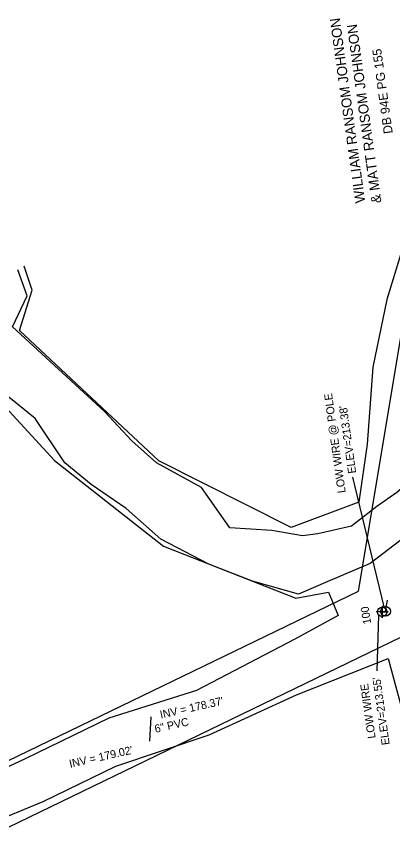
# Model space of a CAD drawing. Extents: x 2317197 to 2318671, y 941884 to 943470.
# Drawn here: x 2318237.5 to 2318425.8, y 942551.5 to 942958 of the extents above; entities that cross this region are included whole.
import ezdxf

# ---------------------------------------------------------------- set-up
doc = ezdxf.new("R2010")
doc.units = 0
for name, color, linetype in [('Default Symbol CELL', 7, 'Continuous'), ('Default Symbol Leader', 7, 'Continuous'), ('Default Symbol Text', 7, 'Continuous'), ('Exist Hydro Jurisdictional Stream or Body of Water', 7, 'Continuous'), ('Exist Property Deed Book Text', 7, 'Continuous'), ('Exist Property Owner Text', 7, 'Continuous'), ('Exist Right of Way Easement Line', 7, 'Continuous'), ('Exist Right of Way Line', 7, 'Continuous'), ('Exist Structure Minor Pipes HDPE 8 Inch', 7, 'Continuous'), ('Exist Structure Minor Pipes HDPE 8 Inch Invert', 7, 'Continuous'), ('Exist Structure Minor Pipes HDPE 8 Inch Text', 7, 'Continuous'), ('Exist Utilities Power Pole CELL', 7, 'Continuous'), ('Exist Utilities Power Pole Text', 7, 'Continuous'), ('Exist Utilities Power Tower CELL', 7, 'Continuous'), ('Exist Vegetation Woods Line', 7, 'Continuous')]:
    doc.layers.add(name, color=color, linetype=linetype)

msp = doc.modelspace()

# ---------------------------------------------------------------- linework, layer by layer
at = {"layer": 'Default Symbol CELL'}
msp.add_lwpolyline([(2318420.6, 942663.37), (2318420.6, 942657.37), (2318420.6, 942660.37), (2318423.6, 942660.37), (2318417.6, 942660.37)], dxfattribs=at)
msp.add_circle((2318420.6, 942660.37), 2.34, dxfattribs=at)
at = {"layer": 'Default Symbol Leader'}
for p, q in [((2318421.59, 942662.95), (2318405.83, 942727.77)), ((2318418.76, 942658.73), (2318417.93, 942630.96))]:
    msp.add_line(p, q, dxfattribs=at)
at = {"layer": 'Exist Hydro Jurisdictional Stream or Body of Water'}
for points in [[(2318535.3, 942771.47), (2318515.83, 942752.18), (2318496, 942738.2), (2318475.44, 942726.82), (2318457.48, 942715.87), (2318430.01, 942696.42), (2318414.58, 942684.49), (2318393.33, 942675.63), (2318378.71, 942669.17), (2318355.7, 942675.78), (2318333.76, 942684.19), (2318309.82, 942696.76), (2318292.41, 942712.02), (2318274.96, 942724.1), (2318261.75, 942734.87), (2318247.01, 942757.06), (2318227.38, 942772.58), (2318210.69, 942790.86), (2318212.07, 942815.47), (2318215.15, 942836)], [(2318501.27, 942779.19), (2318500.65, 942776.96), (2318478.91, 942758.04), (2318462.02, 942748.9), (2318427.82, 942719.95), (2318417.95, 942713.05), (2318405.14, 942703.16), (2318388.37, 942699.42), (2318380.68, 942698.39), (2318365.37, 942700.99), (2318344.41, 942702.3), (2318330.15, 942722.49), (2318307.69, 942734.85), (2318295.39, 942745.8), (2318281.66, 942760.54), (2318235.65, 942802.84), (2318243.03, 942818.33), (2318238.27, 942831.28)]]:
    msp.add_lwpolyline(points, dxfattribs=at)
at = {"layer": 'Exist Right of Way Easement Line'}
for p, q in [((2318408.71, 942670.8), (2318541.09, 943465.13)), ((2317580.08, 942269.97), (2318408.71, 942670.8)), ((2317593.15, 942242.96), (2318435.75, 942650.55))]:
    msp.add_line(p, q, dxfattribs=at)
at = {"layer": 'Exist Right of Way Line'}
msp.add_arc((2317727.3, 942999.3), 843.45, 316.84604, 328.85352, dxfattribs=at)
at = {"layer": 'Exist Structure Minor Pipes HDPE 8 Inch'}
msp.add_lwpolyline([(2318304.81, 942607.98), (2318304.15, 942595.82)], dxfattribs=at)
at = {"layer": 'Exist Utilities Power Pole CELL'}
for q in [(2318423.15, 942666.23), (2318422.23, 942660.68)]:
    msp.add_line((2318422.23, 942660.68), q, dxfattribs=at)
msp.add_circle((2318422.23, 942660.68), 2.45, dxfattribs=at)
at = {"layer": 'Exist Utilities Power Tower CELL'}
msp.add_line((2318422.23, 942660.68), (2318422.23, 942660.68), dxfattribs=at)
at = {"layer": 'Exist Vegetation Woods Line'}
for points in [[(2318439.89, 942893.47), (2318433.09, 942849.59), (2318422.93, 942816.4), (2318415.85, 942782.65), (2318413.04, 942744.11), (2318408.91, 942715.28), (2318374.97, 942702.57), (2318308.9, 942735.93), (2318239.12, 942801.05), (2318245.53, 942821.1), (2318241.39, 942833.19)], [(2318207.34, 942837.53), (2318207.34, 942789.44), (2318256.63, 942735.95), (2318311.14, 942693.24), (2318377.34, 942667.16), (2318393.73, 942670.29), (2318398.49, 942658.49), (2318376.81, 942646.78), (2318327.72, 942621.04), (2318283.89, 942607.22), (2318242, 942586.89), (2318197.3, 942566.1), (2318149.43, 942545.66), (2318104.96, 942522.15), (2318066.57, 942501.46)], [(2317566.47, 942252.86), (2317585.52, 942245.38), (2317614.8, 942257.62), (2317655.31, 942278.17), (2317696.98, 942297.95), (2317735.39, 942318.15), (2317779.98, 942340.46), (2317814.58, 942353.56), (2317855.74, 942373.52), (2317898.59, 942394.26), (2317941.65, 942416.26), (2317988.39, 942435.8), (2318033.15, 942458.71), (2318078.29, 942479), (2318117.02, 942498.93), (2318158.1, 942521.54), (2318202.74, 942545.82), (2318250.98, 942565.6), (2318287.39, 942583.35), (2318333.94, 942598.89), (2318377.64, 942618.89), (2318423.51, 942637.15), (2318431.19, 942608.76), (2318442.13, 942565.53)]]:
    msp.add_lwpolyline(points, dxfattribs=at)

# ---------------------------------------------------------------- texts
at = {"layer": 'Default Symbol Text'}
for s, p in [('LOW WIRE @ POLE', (2318402.34, 942720.02)), ("ELEV=213.38' ", (2318407.55, 942729.79)), ('LOW WIRE', (2318417.31, 942597.35)), ("ELEV=213.55' ", (2318424.33, 942594.11))]:
    msp.add_text(s, height=4, rotation=97.902, dxfattribs=at).set_placement(p)
at = {"layer": 'Exist Property Deed Book Text'}
msp.add_text('DB 94E PG 155', height=4.5, rotation=97.8328, dxfattribs=at).set_placement((2318425.87, 942899.6))
at = {"layer": 'Exist Property Owner Text'}
for s, p in [('WILLIAM RANSOM JOHNSON', (2318412.12, 942865.07)), ('& MATT RANSOM JOHNSON', (2318420.22, 942864.92))]:
    msp.add_text(s, height=5, rotation=97.902, dxfattribs=at).set_placement(p)
at = {"layer": 'Exist Structure Minor Pipes HDPE 8 Inch Invert'}
for s, p in [("INV = 178.37'", (2318309.85, 942607.01)), ("INV = 179.02'", (2318264.48, 942582.45))]:
    msp.add_text(s, height=4, rotation=12.6601, dxfattribs=at).set_placement(p)
at = {"layer": 'Exist Structure Minor Pipes HDPE 8 Inch Text'}
msp.add_text('6" PVC', height=4, rotation=12.6601, dxfattribs=at).set_placement((2318307.22, 942599.91))
at = {"layer": 'Exist Utilities Power Pole Text'}
msp.add_text('100', height=4, rotation=99.5989, dxfattribs=at).set_placement((2318415.11, 942654.55))

doc.saveas('drawing.dxf')
